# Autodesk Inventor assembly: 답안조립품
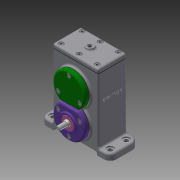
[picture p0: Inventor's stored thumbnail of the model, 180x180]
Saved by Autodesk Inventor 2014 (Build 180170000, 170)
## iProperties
Created: 2020-05
Part Number: 답안조립품
Document SubType Name: Assembly
Designer: kh
Mass: 1076.75 g
Surface Area: 1575.48 cm^2
Volume: 384.079 cm^3
Density: 2.80345 g/cm^3
Author: kh
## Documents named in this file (24)
- C:\Users\kh\Desktop\600506V1024\답안조립품.iam
- C:\Users\kh\Desktop\600506V1024\본체.ipt
- C:\Users\kh\Desktop\600506V1024\개스킷 A.ipt
- C:\Users\kh\Desktop\600506V1024\개스킷 B.ipt
- C:\Users\kh\Desktop\600506V1024\개스킷 C.ipt
- C:\Users\kh\Desktop\600506V1024\베어링 6001.ipt
- 베어링 6001.ipt
- C:\Users\kh\Desktop\600506V1024\베어링 6002.ipt
- 베어링 6002.ipt
- C:\Users\kh\Desktop\600506V1024\볼트 M4.ipt
- C:\Users\kh\Desktop\600506V1024\스퍼기어 A.ipt
- C:\Users\kh\Desktop\600506V1024\스퍼기어 B.ipt
- C:\Users\kh\Desktop\600506V1024\오일 실 10 20 7.ipt
- C:\Users\kh\Desktop\600506V1024\오일 실 12 22 7.ipt
- C:\Users\kh\Desktop\600506V1024\축 A.ipt
- C:\Users\kh\Desktop\600506V1024\축 B.ipt
- C:\Users\kh\Desktop\600506V1024\칼라.ipt
- C:\Users\kh\Desktop\600506V1024\커버 A.ipt
- C:\Users\kh\Desktop\600506V1024\커버 B.ipt
- C:\Users\kh\Desktop\600506V1024\커버 C.ipt
- C:\Users\kh\Desktop\600506V1024\커버 D.ipt
- C:\Users\kh\Desktop\600506V1024\커버 E.ipt
- C:\Users\kh\Desktop\600506V1024\키 4 x 4 x 12.ipt
- C:\Users\kh\Desktop\600506V1024\키 5 x 5 x 12.ipt
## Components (5 placed, 3 different names)
1. 개스킷 A:1
2. 개스킷 C:1
3. 개스킷 B:1
4. 개스킷 B:2
5. 개스킷 B:3
